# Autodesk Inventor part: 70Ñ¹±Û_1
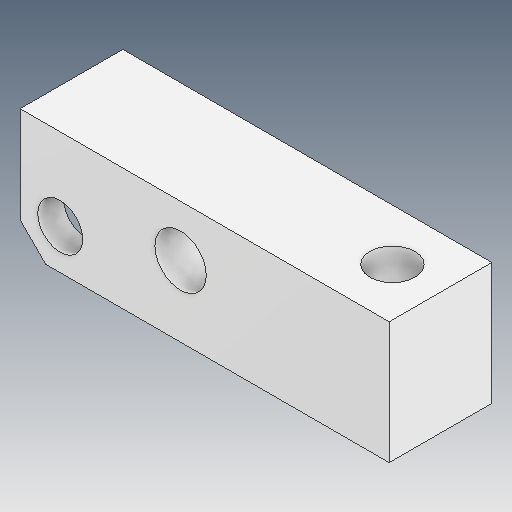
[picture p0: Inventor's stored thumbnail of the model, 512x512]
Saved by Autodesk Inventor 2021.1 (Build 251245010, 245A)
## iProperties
Created: 2021-05
Part Number: 70Ñ¹±Û_1
Material: Ogólny
Document SubType Name: Modeling
Designer: user
Density: 1 g/cm^3
Appearance: Domyślna
Author: user
Revision Number: ÈÎºÎ
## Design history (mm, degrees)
feature "ÊäÈë1"
node "Bryła1"
